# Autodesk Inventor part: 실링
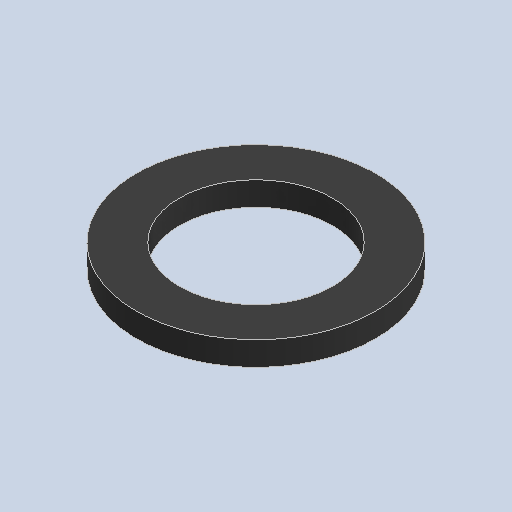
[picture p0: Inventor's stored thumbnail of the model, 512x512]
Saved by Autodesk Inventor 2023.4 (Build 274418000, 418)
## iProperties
Created: 2024-11
Part Number: 실링
Material: 고무
Document SubType Name: Modeling
Designer: EDU
Density: 0.93 g/cm^3
Appearance: 기본값
Author: jhkim
Sending System: Autodesk Inventor 2025
Preprocessor: ST-DEVELOPER v20
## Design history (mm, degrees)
feature "솔리드1"
node "솔리드2"
